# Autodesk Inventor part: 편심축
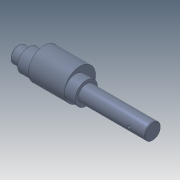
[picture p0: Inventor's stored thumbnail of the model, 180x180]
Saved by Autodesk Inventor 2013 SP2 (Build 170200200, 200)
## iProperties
Manager: 한국ATC센터
Company: 한국ATC센터
Created: 2014-07
Part Number: 편심축
Document SubType Name: Modeling
Designer: KYOUNG IL JANG
Density: 7.86 g/cm^3
Material: 강, 연강
Mass: 1544.74 g
Surface Area: 256.354 cm^2
Volume: 196.531 cm^3
Author: KYOUNG IL JANG
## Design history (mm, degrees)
sketch "스케치1"
  geometry: L1 (-105, 0)-(105, 0); L2 (-105, 0)-(-105, 12.5); L3 (-105, 12.5)-(-89, 12.5); L4 (-89, 12.5)-(-89, 17.5); L5 (-89, 17.5)-(-82, 17.5); L6 (-82, 17.5)-(-82, 12.5); L7 (-82, 12.5)-(-0.35, 12.5); L8 (-0.35, 12.5)-(-0.35, 11.95); L9 (-0.35, 11.95)-(1, 11.95); L10 (1, 11.95)-(1, 12.5); L11 (1, 12.5)-(105, 12.5); L12 (105, 12.5)-(105, 0); L13 (70, 12.5)-(70, 9.1); L14 (70, 9.1)-(95, 9.1); L15 (95, 9.1)-(95, 12.5); L16 (80, -12.5)-(82.5, -12.5); L17 (82.5, -12.5)-(80, -10); L18 (80, -10)-(80, -12.5); L19 (1, 12.5)-(-0.35, 12.5); 2 further points
  constraints: 38 end point, 8 parallel, 5 collinear, 5 perpendicular, 2 point on line, 1 coincident, 1 horizontal, 1 midpoint, 1 vertical
  dimensions: "d0" = 210 distance of L1.start L1.end; "d1" = 25 diameter of L3 L1; "d2" = 35 diameter of L5 L1; "d3" = 16 distance of L2.end L3.end; "d6" = 1.35 distance of L8.end L9.end; "d7" = 23.9 diameter of L9 L1; "d8" = 3.4 distance between parallel lines of L14 L11; "d9" = 10 distance between parallel lines of L15 L12; "d10" = 25 distance of L13.end L14.end; "d11" = 25 diameter of L16 L1 (= d1); "d12" = 25 distance from line of L12 L16.start; "d13" = 45 deg angle of L17 L18; "d14" = 5 diameter of L16.end L18; "d27" = 104 distance between parallel lines of L10 L12; "d35" = 7 distance of L4.end L5.end
revolve "회전1" stored, may be unused: angle "d15" = 90 deg
revolve "회전2" stored, may be unused: angle "d16" = 90 deg
extrude "돌출1" cut sketch "스케치1" stored distance "d17" = 8; taper "d18" = 0 deg
fillet "모깎기1" dims "d19" = 4
node "작업 평면1"
sketch "스케치2"
  geometry: C1 r 12.5 at (0, 0) reference; C2 r 17.5 at (0, 0); C3 r 24.5 at (0, 7); 1 further point
  constraints: 2 centre point, 1 coincident, 1 tangent, 1 vertical alignment
  dimensions: "d32" = 35 diameter of C2; "d33" = 49 diameter of C3 (derived); "d34" = 7 distance of C3.centre point (0, 0)
extrude "돌출2" join sketch "스케치2" distance "d22" = 56; taper "d23" = 0 deg
chamfer "모따기1" distance "d24" = 1; stored, may be unused: second distance "d25" = 2, angle "d26" = 45 deg
feature "면 이동1" dims "d31" = 83
node "솔리드1"
